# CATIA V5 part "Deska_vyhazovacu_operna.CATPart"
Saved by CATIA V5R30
Part number: Deska_vyhazovacu_operna
Definition: F 85_346446_218_22_1730
Nomenclature: F 85_346446_218_22_1730
Source: Unknown
Description: PART--DESC
Bounding box of the stored display mesh (mm): x -223 to 223, y -109 to 109, z -220 to -198
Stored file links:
  E:\Bakalarka\Model\Forma_v7\Deska_vyhazovacu_operna.CATPart
  E:\Bakalarka\Model\Sestava_formy_1\Sestava_vyhazovacu.CATProduct
  E:\Bakalarka\Model\Forma_v7\Sestava_vyhazovacu.CATProduct
  E:\Bakalarka\Model\Chyba catie 2\Forma_Sestava_vyhazovacu.CATPart
  E:\Bakalarka\Model\Forma_v7\Forma_Sestava_vyhazovacu.CATPart
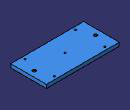
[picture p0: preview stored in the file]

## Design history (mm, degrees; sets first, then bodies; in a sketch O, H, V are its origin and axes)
Body1 "MANIFOLD_SOLID_BREP #4098" (main body)
  Solid1: solid without history
  Sketch1 on face of Solid1, origin (0, 0, -220), H (1, 0, 0), V (0, -1, 0)
    point P1 (0, 0)
    coincidence: P1 O
  Sketch2 on face of Solid1, origin (0, 0, -220), H (1, 0, 0), V (0, -1, 0)
    point P1 (0, 0)
    reference projected point E1 (0, 0) from Sketch1.P1
    coincidence: E1 P1
  Hole1: placed by Sketch2, at (0, 0, -220) direction (0, 0, 1), diameter 8.376, through (limit type 6), threaded "M10", thread diameter 10, thread depth 22, pitch 1.5
  Body2 "Result of DrillHole"
    Solid2: linked copy from another document
  Assemble1 "DrillHoleLeaderPin_E1010_1.1": tool Body2
  Body3 "Result of DrillHole"
    Solid3: linked copy from another document
  Assemble2 "DrillHoleLeaderPin_E1010_1.2": tool Body3
  Body4 "Result of DrillHole"
    Solid4: linked copy from another document
  Assemble3 "DrillHoleBushing_E1105_1.3": tool Body4
  Body5 "Result of DrillHole"
    Solid5: linked copy from another document
  Assemble4 "DrillHoleBushing_E1105_1.4": tool Body5
  DatumCurve1
  DatumCurve2
  Sketch3 on face of Solid1, origin (0, 0, -198), H (1, 0, 0), V (0, 1, 0)
    projected circle E1 centre (188, 0) radius 10 from edge of DatumCurve1
    projected circle E2 centre (-188, 0) radius 10 from edge of DatumCurve2
  Pocket1: profile Sketch3, direction (0, 0, -1), length 6
  Body6 "Result of DrillHole"
    Solid6: linked copy from another document
  Assemble5 "DrillHoleLeaderPin_E1010_1.3": tool Body6
  Body7 "Result of DrillHole"
    Solid7: linked copy from another document
  Assemble6 "DrillHoleLeaderPin_E1010_1.4": tool Body7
